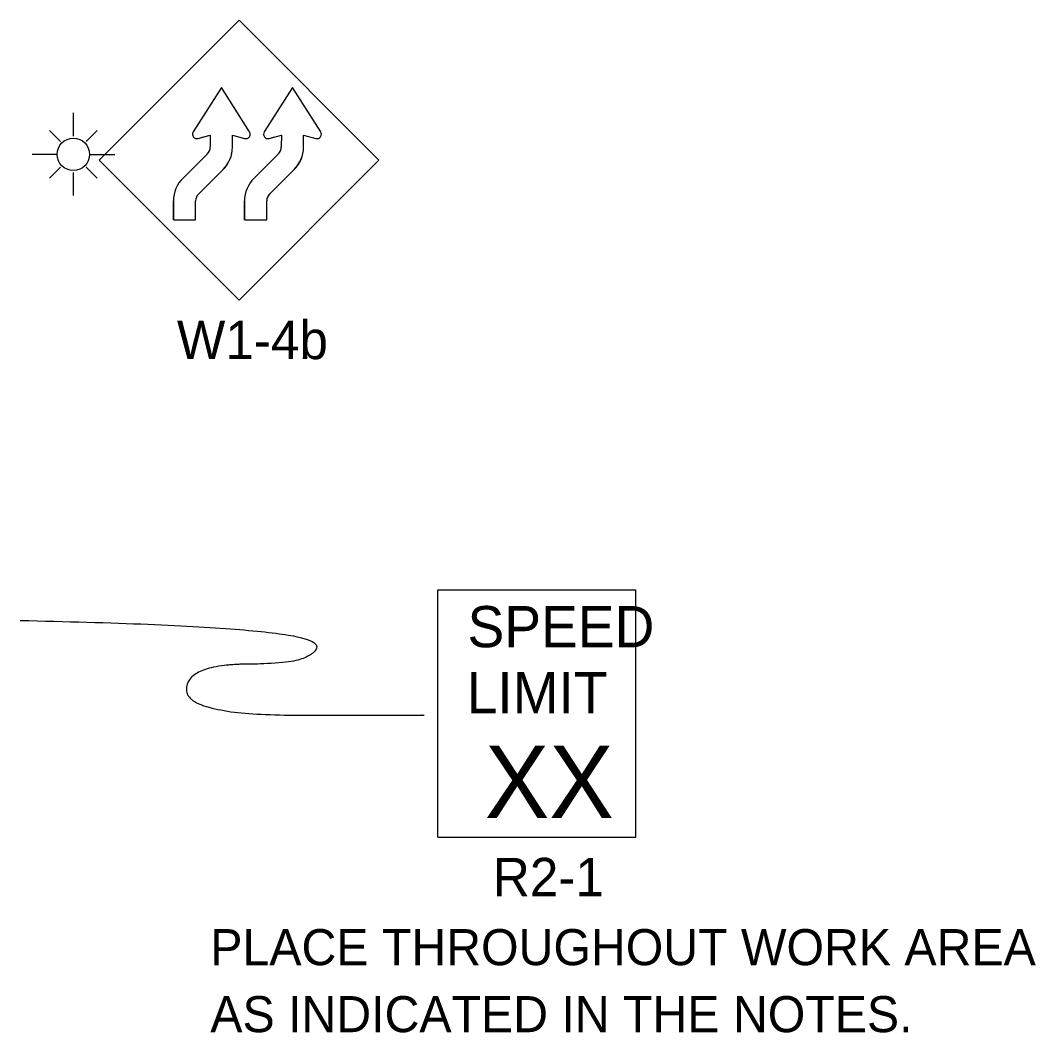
# Model space of a CAD drawing. Extents: x 16731 to 19504, y 5932 to 7446.
# Drawn here: x 17223.9 to 17421, y 6275.3 to 6471.7 of the extents above; entities that cross this region are included whole.
import ezdxf

# ---------------------------------------------------------------- set-up
doc = ezdxf.new("R2010")
doc.units = 0
doc.layers.add('TRAFFIC_SIGNS_PR', color=7, linetype='Continuous')
doc.layers.add('TYPICAL_TEXT_DIMEN_PR', color=7, linetype='Continuous')

msp = doc.modelspace()

# ---------------------------------------------------------------- linework, layer by layer
at = {"layer": 'TRAFFIC_SIGNS_PR'}
for p, q in [((17266.35, 6471.7), (17239.2, 6444.55)), ((17293.5, 6444.55), (17266.35, 6471.7)), ((17234.2, 6449.25), (17234.2, 6453.75)), ((17231.68, 6448.21), (17229.58, 6450.31)), ((17236.71, 6448.21), (17238.82, 6450.31)), ((17231.04, 6445.69), (17226.2, 6445.69)), ((17237.35, 6445.69), (17242.23, 6445.69)), ((17255.48, 6441.08), (17260.2, 6445.79)), ((17260.2, 6445.79), (17255.48, 6441.08)), ((17269.28, 6441.08), (17273.99, 6445.79)), ((17273.99, 6445.79), (17269.28, 6441.08)), ((17239.2, 6444.55), (17266.35, 6417.39)), ((17266.35, 6417.39), (17293.5, 6444.55)), ((17231.68, 6443.18), (17229.58, 6441.07)), ((17234.2, 6437.73), (17234.2, 6442.14)), ((17236.71, 6443.18), (17238.82, 6441.07)), ((17258.53, 6438.03), (17263.25, 6442.74)), ((17258.54, 6438.03), (17263.25, 6442.74)), ((17272.33, 6438.03), (17277.04, 6442.74)), ((17272.33, 6438.03), (17277.04, 6442.74)), ((17253.62, 6432.96), (17253.62, 6436.66)), ((17257.93, 6432.96), (17257.93, 6436.66)), ((17267.41, 6432.96), (17267.41, 6436.66)), ((17271.73, 6432.96), (17271.73, 6436.66)), ((17253.62, 6432.96), (17257.93, 6432.96)), ((17267.41, 6432.96), (17271.73, 6432.96)), ((17304.93, 6361.19), (17343.33, 6361.19)), ((17304.93, 6313.19), (17304.93, 6361.19)), ((17343.33, 6313.19), (17343.33, 6361.19)), ((17304.93, 6313.19), (17343.33, 6313.19))]:
    msp.add_line(p, q, dxfattribs=at)
for points in [[(17268.4, 6450.07), (17262.92, 6458.68), (17257.44, 6450.07)], [(17268.4, 6450.07), (17262.92, 6458.68), (17257.44, 6450.07)], [(17282.2, 6450.07), (17276.72, 6458.68), (17271.24, 6450.07)], [(17282.2, 6450.07), (17276.72, 6458.68), (17271.24, 6450.07)], [(17258.4, 6448.77), (17260.76, 6449.42), (17260.76, 6447.12)], [(17258.4, 6448.77), (17259.23, 6449), (17260.76, 6449.42), (17260.76, 6447.12)], [(17265.07, 6447.05), (17265.08, 6449.42), (17267.44, 6448.77)], [(17265.07, 6447.05), (17265.08, 6449.42), (17267.44, 6448.77)], [(17272.2, 6448.77), (17274.56, 6449.42), (17274.55, 6447.12)], [(17272.2, 6448.77), (17273.03, 6449), (17274.56, 6449.42), (17274.55, 6447.12)], [(17278.87, 6447.05), (17278.87, 6449.42), (17281.24, 6448.77)], [(17278.87, 6447.05), (17278.87, 6449.42), (17281.24, 6448.77)], [(17253.61, 6436.66), (17253.62, 6432.96), (17257.93, 6432.96), (17257.93, 6436.66)], [(17267.41, 6436.66), (17267.41, 6432.96), (17271.73, 6432.96), (17271.73, 6436.66)]]:
    msp.add_lwpolyline(points, dxfattribs=at)
msp.add_circle((17234.2, 6445.69), 3.15, dxfattribs=at)
for centre, radius, start, end in [((17258.17, 6449.6), 0.864, 147.5204, 285.3986), ((17258.17, 6449.6), 0.866, 147.5288, 285.3852), ((17267.67, 6449.61), 0.866, 254.6828, 32.2708), ((17267.67, 6449.61), 0.866, 254.6799, 32.2804), ((17277.51, 6455.87), 10.8, 212.4569, 212.4665), ((17271.97, 6449.6), 0.864, 147.5204, 285.3986), ((17271.97, 6449.6), 0.866, 147.5288, 285.3852), ((17281.47, 6449.61), 0.866, 254.6828, 32.2708), ((17281.47, 6449.61), 0.866, 254.6799, 32.2804), ((17291.31, 6455.87), 10.8, 212.4569, 212.4665), ((17264.59, 6438.35), 10.8, 74.68, 74.6808), ((17278.38, 6438.35), 10.8, 74.68, 74.6808), ((17258.91, 6447.12), 1.85, 314.2125, 0), ((17258.91, 6447.12), 1.85, 314.2123, 0.1238), ((17258.91, 6447.12), 6.17, 314.2125, 359.3819), ((17258.91, 6447.12), 6.17, 314.7687, 359.3755), ((17272.7, 6447.12), 1.85, 314.2125, 0), ((17272.7, 6447.12), 1.85, 314.2123, 0.1238), ((17272.7, 6447.12), 6.17, 314.2125, 359.3819), ((17272.7, 6447.12), 6.17, 314.7687, 359.3755), ((17259.78, 6436.66), 6.17, 134.2117, 180), ((17259.78, 6436.66), 6.17, 134.2125, 180), ((17259.78, 6436.66), 6.17, 134.2125, 180), ((17273.58, 6436.66), 6.17, 134.2125, 180), ((17273.58, 6436.66), 6.17, 134.2125, 180), ((17273.58, 6436.66), 6.17, 134.2117, 180), ((17259.78, 6436.66), 1.85, 132.372, 180), ((17259.78, 6436.66), 1.85, 134.2125, 180), ((17273.58, 6436.66), 1.85, 132.372, 180), ((17273.58, 6436.66), 1.85, 134.2125, 180)]:
    msp.add_arc(centre, radius, start, end, dxfattribs=at)
at = {"layer": 'TYPICAL_TEXT_DIMEN_PR'}
msp.add_open_spline([(17223.9, 6355.27), (17281.31, 6354.04), (17281.31, 6346.78), (17256.13, 6346.78), (17256.13, 6336.87), (17299.78, 6336.87), (17302.3, 6336.87)], degree=2, dxfattribs=at)

# ---------------------------------------------------------------- texts
at = {"layer": 'TRAFFIC_SIGNS_PR'}
for s, height, p in [('W1-4b', 7.44, (17254.3, 6405.95)), ('SPEED', 8, (17310.69, 6350.05)), ('LIMIT', 8, (17310.53, 6337.25)), ('XX', 14.031, (17314.04, 6316.95)), ('R2-1', 7.44, (17315.6, 6301.75)), ('PLACE THROUGHOUT WORK AREA', 7, (17260.78, 6288.36)), ('AS INDICATED IN THE NOTES.', 7, (17260.78, 6275.36))]:
    msp.add_text(s, height=height, dxfattribs=at).set_placement(p)

doc.saveas('drawing.dxf')
